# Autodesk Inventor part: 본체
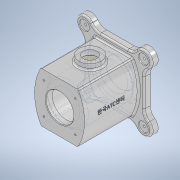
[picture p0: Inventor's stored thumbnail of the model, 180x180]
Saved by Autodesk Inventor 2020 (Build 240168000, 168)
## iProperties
Created: 2022-01
Part Number: 본체
Material: 알루미늄 6061
Document SubType Name: Modeling
Designer: USER
Density: 2.7 g/cm^3
Appearance: 알루미늄 - 연마
Mass: 1283.64 g
Surface Area: 918.697 cm^2
Volume: 475.421 cm^3
Author: USER
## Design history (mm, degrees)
sketch "스케치1"
  geometry: L1 (-54, -54)-(54, 54); L2 (-54, -25.008)-(-54, 25.008); L3 (-25.008, 54)-(25.008, 54); L4 (54, -54)-(51.619, -51.619); L5 (0, 0)-(-54, 54); L6 (54, 25.008)-(54, -25.008); L7 (25.008, -54)-(-25.008, -54); C1 r 2 at (-53.033, 53.033); C2 r 2 at (53.033, 53.033); C3 r 2 at (-53.033, -53.033); A1 r 75 centre (0, 0) between (-53.033, 53.033) and (53.033, 53.033); A2 r 15 centre (-53.033, 53.033) between (-41.022, 62.019) and (-62.019, 41.022); A3 r 15 centre (53.033, 53.033) between (62.019, 41.022) and (41.022, 62.019); A4 r 15 centre (53.033, -53.033) between (41.022, -62.019) and (62.019, -41.022); A5 r 15 centre (-53.033, -53.033) between (-62.019, -41.022) and (-41.022, -62.019); A6 r 20 centre (-74, 25.008) between (-54, 25.008) and (-62.019, 41.022); A7 r 20 centre (-25.008, 74) between (-41.022, 62.019) and (-25.008, 54); A8 r 20 centre (25.008, 74) between (25.008, 54) and (41.022, 62.019); A9 r 20 centre (74, 25.008) between (62.019, 41.022) and (54, 25.008); A10 r 20 centre (74, -25.008) between (54, -25.008) and (62.019, -41.022); A11 r 20 centre (25.008, -74) between (41.022, -62.019) and (25.008, -54); A12 r 20 centre (-25.008, -74) between (-25.008, -54) and (-41.022, -62.019); A13 r 20 centre (-74, -25.008) between (-62.019, -41.022) and (-54, -25.008); 9 further points
  constraints: 36 point on circle, 16 centre point, 16 tangent, 14 end point, 12 point on line, 11 equal radius, 5 coincident, 2 parallel, 1 horizontal, 1 midpoint, 1 perpendicular, 5 other
  dimensions: "d0" = 108 distance of L5.end L1.end; "d1" = 108 distance of L1.start L5.end; "d2" = 150 diameter of A1; "d3" = 30 diameter of A2; "d4" = 4 diameter of C1; "d5" = 20 radius of A6
extrude "돌출1" new body sketch "스케치1" distance "d6" = 12; taper "d7" = 0 deg
sketch "스케치2"
  geometry: L1 (33.054, -45)-(-33.054, -45); L2 (-45, -0.086)-(-45, 0.606); L3 (-33.724, 45)-(33.724, 45); L4 (45, 0.606)-(45, -0.086); L5 (45, -45)-(-45, 45); L6 (-45, -45)-(45, 45); L7 (0, 47.952)-(0, -51.745); L8 (-62.777, -0.086)-(68.35, -0.086); A1 r 93.031 centre (48.031, 0.606) between (-33.724, 45) and (-33.054, -45); A2 r 93.031 centre (-48.031, 0.606) between (33.054, -45) and (33.724, 45); 1 further point
  constraints: 16 end point, 6 point on circle, 3 symmetric about line, 2 centre point, 2 horizontal, 2 midpoint, 2 parallel, 2 point on line, 2 tangent, 1 perpendicular, 1 vertical, 1 other
  dimensions: "d8" = 90 distance of L5.end L6.end; "d9" = 90 distance of L6.end L5.start; "d10" = 93.03134 radius of A1; "d11" = 45.08642 distance between parallel lines of L8 L3; "d12" = 23.35019 distance from line of L8.end L4; "d13" = 0.69257 distance from line of A1.centre L8; "d14" = 48.03796 distance from line of L7.start L8; "d15" = 51.65905 distance from line of L7.end L8; "d16" = 107.77673 distance from line of L8.start L4
extrude "돌출2" join sketch "스케치2" distance "d17" = 98; taper "d18" = 0 deg
node "작업 평면1"
node "작업 평면3"
  node "작업 평면2"
sketch "스케치3"
  geometry: L1 (58.733, 12)-(8.716, 12) reference; C1 r 20 at (33.724, -43); 1 further point
  constraints: 1 centre point
  dimensions: "d21" = 40 diameter of C1; "d22" = 55 distance from line of L1 C1.centre
extrude "돌출3" join sketch "스케치3" distance "d23" = 30; taper "d24" = 0 deg
sketch "스케치4"
  geometry: C1 r 25 at (0, 0); 1 further point
  constraints: 1 centre point, 1 coincident
  dimensions: "d25" = 50 diameter of C1
extrude "돌출4" cut sketch "스케치4" extent not by distance; stored distance "d26" = 0; taper "d27" = 0 deg
node "작업 평면4"
sketch "스케치5"
  geometry: C1 r 37 at (0, 0); 1 further point
  constraints: 1 centre point, 1 coincident
  dimensions: "d29" = 74 diameter of C1
extrude "돌출5" cut sketch "스케치5" distance "d30" = 86; taper "d31" = 0 deg
sketch "스케치6"
  geometry: 1 further point
fillet "모깎기1" dims "d32" = 3
chamfer "모따기1" distance "d33" = 1; stored, may be unused: second distance "d34" = 2, angle "d35" = 45 deg
fillet "모깎기2" dims "d36" = 3
sketch "스케치7" dims "d37" = 80
  geometry: L1 (0, -59.816)-(0, 86.365) reference; L2 (-67.972, 0)-(59.976, 0) reference; L3 (0, 0)-(-58.946, 58.946); 2 further points
  constraints: 6 end point, 2 horizontal, 2 vertical, 1 coincident, 1 point on line, 3 other
  dimensions: "d38" = 45 deg angle of L3 L1
hole "구멍1" sketch "스케치7" at (-28.284, 28.284) diameter "d39" = 3.242; stored, may be unused: countersink angle "d43" = 90 deg, drill point angle "d45" = 118 deg; dims "d40" = 9, "d41" = 4, "d42" = 2, "d44" = 11
sketch "스케치8"
  geometry: C1 r 2 at (-53.033, 53.033) reference; C2 r 9 at (-53.033, 53.033); C3 r 2 at (53.033, 53.033) reference; C4 r 9 at (53.033, 53.033); 1 further point
  constraints: 2 centre point, 2 coincident, 1 equal radius
  dimensions: "d49" = 18 diameter of C2
extrude "돌출6" cut sketch "스케치8" distance "d50" = 2; taper "d51" = 0 deg
sketch "스케치9"
  geometry: C1 r 20 at (0, 0) reference; C2 r 12 at (0, 0); 1 further point
  constraints: 1 centre point, 1 coincident
  dimensions: "d52" = 24 diameter of C2
extrude "돌출7" cut sketch "스케치9" distance "d53" = 24; taper "d54" = 0 deg
node "작업 평면5"
sketch "스케치10"
  geometry: C1 r 12 at (31.92, -40) reference; C2 r 15 at (31.92, -40); 1 further point
  constraints: 1 centre point, 1 coincident
  dimensions: "d56" = 30 diameter of C2
extrude "돌출8" cut sketch "스케치10" distance "d57" = 24; taper "d58" = 0 deg
sketch "스케치11"
  geometry: 1 further point
fillet "모깎기3" dims "d59" = 1
sketch "스케치12"
  geometry: L1 (0, 0)-(0, 93.648) reference; L2 (0, 0)-(90.053, 0) reference; L3 (0, 0)-(82.995, 82.995); C1 r 40 at (0, 0); C2 r 25 at (0, 0) reference; C3 r 34 at (0, 0) reference; C4 r 1.621 at (28.284, 28.284) reference; 2 further points
  constraints: 6 end point, 2 coincident, 2 horizontal, 2 vertical, 1 centre point
  dimensions: "d60" = 80 diameter of C1; "d61" = 45 deg angle of L2 L3
hole "구멍2" sketch "스케치12" at (28.284, 28.284) diameter "d62" = 3.242; stored, may be unused: countersink angle "d66" = 90 deg, drill point angle "d68" = 118 deg; dims "d63" = 9, "d64" = 4, "d65" = 2, "d67" = 11
node "작업 평면7"
  node "작업 평면6"
sketch "스케치13"
  geometry: 2 further points
  constraints: 1 other
feature "엠보싱1" sketch "스케치13" dims "d1" = 108, "d73" = 1, "d74" = 0
chamfer "모따기2" distance "d75" = 1; stored, may be unused: second distance "d76" = 2, angle "d77" = 45 deg
node "솔리드1"
pattern_circular "원형 패턴1" dims angle "d47" = 360 deg
mirror "미러1"
pattern_circular "원형 패턴2" dims angle "d70" = 360 deg
feature "A9D066F2-1C7D-4E18-AEED-F7BC21143FA4" dims "d39" = 3.242, "d40" = 9, "d41" = 4, "d42" = 2, "d43" = 90 deg, "d44" = 11, "d45" = 118 deg
other parameters: "d19" = 0, "d20" = 55, "d28" = -12, "d55" = -13, "d72" = 49.5
